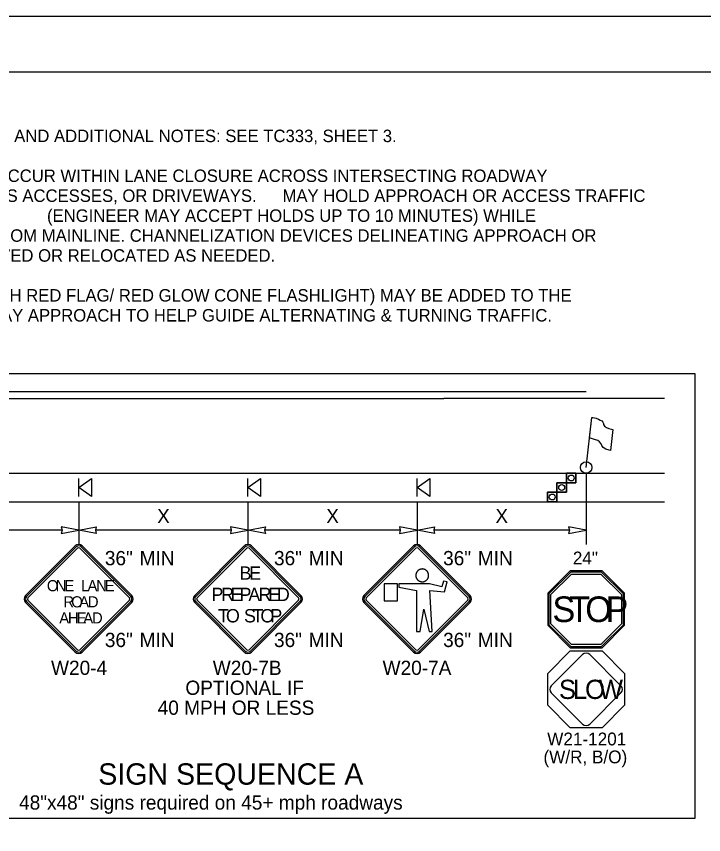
# Model space of a CAD drawing. Extents: x 99999.1 to 100095.7, y 99995 to 100010.7.
# Drawn here: x 100061.34 to 100065.2, y 100006.09 to 100010.687 of the extents above; entities that cross this region are included whole.
import ezdxf

# ---------------------------------------------------------------- set-up
doc = ezdxf.new("R2010")
doc.units = 0
for name, color, linetype in [('RD_ED_ShoulderPavedEdge', 7, 'Continuous'), ('RD_MK_LineDblYellowCenter', 7, 'Continuous'), ('RD_MK_LineEdgeWhite', 7, 'Continuous'), ('RD_MK_LineNoPass', 7, 'Continuous'), ('RD_MK_LineSkipCenter', 7, 'Continuous'), ('SH_DE_DetailHeading2Text', 7, 'Continuous'), ('SH_GI_GeneralNotesBodyText', 7, 'Continuous'), ('SH_GI_PlotLimits', 7, 'Continuous'), ('SH_GI_SheetBorder', 7, 'Continuous'), ('TR_SN_ConstructionSigns', 7, 'Continuous'), ('TR_WZ_FlaggingStation', 7, 'Continuous'), ('TR_WZ_PortableSignMountBlk-Org', 7, 'Continuous'), ('TR_WZ_TrafficCone', 7, 'Continuous'), ('TR_WZ_WorkZoneDetails', 7, 'Continuous'), ('TR_WZ_WorkZoneTextCurrent', 7, 'Continuous')]:
    doc.layers.add(name, color=color, linetype=linetype)

msp = doc.modelspace()

# ---------------------------------------------------------------- linework, layer by layer
at = {"layer": 'RD_ED_ShoulderPavedEdge'}
msp.add_line((100060.3, 100007.9602), (100064.9804, 100007.9602), dxfattribs=at)
at = {"layer": 'RD_MK_LineDblYellowCenter'}
for p, q in [((100060.3, 100008.5802), (100063.7402, 100008.5802)), ((100060.3, 100008.5402), (100063.7402, 100008.5402))]:
    msp.add_line(p, q, dxfattribs=at)
at = {"layer": 'RD_MK_LineEdgeWhite'}
msp.add_line((100060.3, 100008.1202), (100064.9804, 100008.1202), dxfattribs=at)
at = {"layer": 'RD_MK_LineNoPass'}
msp.add_line((100063.7402, 100008.5802), (100064.5402, 100008.5802), dxfattribs=at)
at = {"layer": 'RD_MK_LineSkipCenter'}
msp.add_lwpolyline([(100064.9804, 100008.5402), (100063.7402, 100008.5402)], dxfattribs=at)
at = {"layer": 'SH_GI_PlotLimits'}
msp.add_lwpolyline([(100059.0625, 99999.6875), (100076.0625, 99999.6875), (100076.0625, 100010.6875), (100059.0625, 100010.6875)], close=True, dxfattribs=at)
at = {"layer": 'SH_GI_SheetBorder'}
msp.add_line((100060, 100010.375), (100075.75, 100010.375), dxfattribs=at)
at = {"layer": 'TR_SN_ConstructionSigns'}
for p, q in [((100061.6703, 100007.712), (100061.3919, 100007.4336)), ((100061.6758, 100007.7065), (100061.3974, 100007.428)), ((100061.4051, 100007.4203), (100061.6835, 100007.6987)), ((100061.6968, 100007.6987), (100061.9752, 100007.4203)), ((100061.9829, 100007.428), (100061.7045, 100007.7065)), ((100061.9885, 100007.4336), (100061.71, 100007.712)), ((100062.6203, 100007.712), (100062.3419, 100007.4336)), ((100062.6258, 100007.7065), (100062.3474, 100007.428)), ((100062.3551, 100007.4203), (100062.6335, 100007.6987)), ((100062.6468, 100007.6987), (100062.9252, 100007.4203)), ((100062.9329, 100007.428), (100062.6545, 100007.7065)), ((100062.9385, 100007.4336), (100062.66, 100007.712)), ((100063.5703, 100007.712), (100063.2919, 100007.4336)), ((100063.5758, 100007.7065), (100063.2974, 100007.428)), ((100063.3051, 100007.4203), (100063.5835, 100007.6987)), ((100063.5968, 100007.6987), (100063.8752, 100007.4203)), ((100063.8829, 100007.428), (100063.6045, 100007.7065)), ((100063.8885, 100007.4336), (100063.61, 100007.712)), ((100063.5835, 100007.5502), (100063.5833, 100007.5483)), ((100063.5833, 100007.5483), (100063.5833, 100007.5464)), ((100063.5833, 100007.5464), (100063.5833, 100007.5445)), ((100063.5833, 100007.5445), (100063.5835, 100007.5426)), ((100063.5838, 100007.5522), (100063.5835, 100007.5502)), ((100063.5835, 100007.5426), (100063.5838, 100007.5407)), ((100063.5842, 100007.554), (100063.5838, 100007.5522)), ((100063.5838, 100007.5407), (100063.5842, 100007.5388)), ((100063.5846, 100007.5559), (100063.5842, 100007.554)), ((100063.5842, 100007.5388), (100063.5846, 100007.5369)), ((100063.5852, 100007.5577), (100063.5846, 100007.5559)), ((100063.5858, 100007.5595), (100063.5852, 100007.5577)), ((100063.5865, 100007.5613), (100063.5858, 100007.5595)), ((100063.5873, 100007.563), (100063.5865, 100007.5613)), ((100063.5883, 100007.5647), (100063.5873, 100007.563)), ((100063.5894, 100007.5664), (100063.5883, 100007.5647)), ((100063.5904, 100007.5679), (100063.5894, 100007.5664)), ((100063.5916, 100007.5694), (100063.5904, 100007.5679)), ((100063.5929, 100007.5709), (100063.5916, 100007.5694)), ((100063.5942, 100007.5722), (100063.5929, 100007.5709)), ((100063.5956, 100007.5735), (100063.5942, 100007.5722)), ((100063.5971, 100007.5747), (100063.5956, 100007.5735)), ((100063.5986, 100007.5759), (100063.5971, 100007.5747)), ((100063.6002, 100007.5769), (100063.5986, 100007.5759)), ((100063.6019, 100007.5779), (100063.6002, 100007.5769)), ((100063.6036, 100007.5788), (100063.6019, 100007.5779)), ((100063.6053, 100007.5796), (100063.6036, 100007.5788)), ((100063.6071, 100007.5803), (100063.6053, 100007.5796)), ((100063.6089, 100007.5809), (100063.6071, 100007.5803)), ((100063.6108, 100007.5814), (100063.6089, 100007.5809)), ((100063.6127, 100007.5818), (100063.6108, 100007.5814)), ((100063.6146, 100007.5821), (100063.6127, 100007.5818)), ((100063.6164, 100007.5823), (100063.6146, 100007.5821)), ((100063.6184, 100007.5824), (100063.6164, 100007.5823)), ((100063.6203, 100007.5824), (100063.6184, 100007.5824)), ((100063.6222, 100007.5823), (100063.6203, 100007.5824)), ((100063.6241, 100007.5821), (100063.6222, 100007.5823)), ((100063.626, 100007.5818), (100063.6241, 100007.5821)), ((100063.6279, 100007.5814), (100063.626, 100007.5818)), ((100063.6297, 100007.5809), (100063.6279, 100007.5814)), ((100063.6316, 100007.5803), (100063.6297, 100007.5809)), ((100063.6333, 100007.5796), (100063.6316, 100007.5803)), ((100063.6351, 100007.5788), (100063.6333, 100007.5796)), ((100063.6368, 100007.5779), (100063.6351, 100007.5788)), ((100063.6385, 100007.5769), (100063.6368, 100007.5779)), ((100063.64, 100007.5759), (100063.6385, 100007.5769)), ((100063.6416, 100007.5747), (100063.64, 100007.5759)), ((100063.643, 100007.5735), (100063.6416, 100007.5747)), ((100063.6445, 100007.5722), (100063.643, 100007.5735)), ((100063.6458, 100007.5709), (100063.6445, 100007.5722)), ((100063.647, 100007.5694), (100063.6458, 100007.5709)), ((100063.6482, 100007.5679), (100063.647, 100007.5694)), ((100063.6494, 100007.5664), (100063.6482, 100007.5679)), ((100063.6504, 100007.5647), (100063.6494, 100007.5664)), ((100063.6513, 100007.563), (100063.6504, 100007.5647)), ((100063.6521, 100007.5613), (100063.6513, 100007.563)), ((100063.6529, 100007.5595), (100063.6521, 100007.5613)), ((100063.6535, 100007.5577), (100063.6529, 100007.5595)), ((100063.6541, 100007.5559), (100063.6535, 100007.5577)), ((100063.6545, 100007.554), (100063.6541, 100007.5559)), ((100063.6541, 100007.5369), (100063.6545, 100007.5388)), ((100063.6549, 100007.5522), (100063.6545, 100007.554)), ((100063.6545, 100007.5388), (100063.6549, 100007.5407)), ((100063.6552, 100007.5502), (100063.6549, 100007.5522)), ((100063.6549, 100007.5407), (100063.6552, 100007.5426)), ((100063.6553, 100007.5483), (100063.6552, 100007.5502)), ((100063.6552, 100007.5426), (100063.6553, 100007.5445)), ((100063.6554, 100007.5464), (100063.6553, 100007.5483)), ((100063.6553, 100007.5445), (100063.6554, 100007.5464)), ((100064.4506, 100007.5722), (100064.3241, 100007.4457)), ((100064.4534, 100007.5655), (100064.3308, 100007.4429)), ((100064.3421, 100007.4383), (100064.4581, 100007.5542)), ((100064.6295, 100007.5722), (100064.4506, 100007.5722)), ((100064.6267, 100007.5655), (100064.4534, 100007.5655)), ((100064.4581, 100007.5542), (100064.6221, 100007.5542)), ((100064.6221, 100007.5542), (100064.7381, 100007.4383)), ((100064.7493, 100007.4429), (100064.6267, 100007.5655)), ((100064.7561, 100007.4457), (100064.6295, 100007.5722)), ((100063.4059, 100007.4991), (100063.4059, 100007.4044)), ((100063.4812, 100007.4991), (100063.4059, 100007.4991)), ((100063.4812, 100007.4044), (100063.4812, 100007.4991)), ((100063.6596, 100007.4991), (100063.4882, 100007.4991)), ((100063.4882, 100007.4991), (100063.4882, 100007.481)), ((100063.5846, 100007.5369), (100063.5852, 100007.5351)), ((100063.5852, 100007.5351), (100063.5858, 100007.5333)), ((100063.5858, 100007.5333), (100063.5865, 100007.5315)), ((100063.5865, 100007.5315), (100063.5873, 100007.5298)), ((100063.5873, 100007.5298), (100063.5883, 100007.5281)), ((100063.5883, 100007.5281), (100063.5894, 100007.5265)), ((100063.5894, 100007.5265), (100063.5904, 100007.5249)), ((100063.5904, 100007.5249), (100063.5916, 100007.5234)), ((100063.5916, 100007.5234), (100063.5929, 100007.522)), ((100063.5929, 100007.522), (100063.5942, 100007.5206)), ((100063.5942, 100007.5206), (100063.5956, 100007.5193)), ((100063.5956, 100007.5193), (100063.5971, 100007.5181)), ((100063.5971, 100007.5181), (100063.5986, 100007.5169)), ((100063.5986, 100007.5169), (100063.6002, 100007.5159)), ((100063.6002, 100007.5159), (100063.6019, 100007.5149)), ((100063.6019, 100007.5149), (100063.6036, 100007.514)), ((100063.6036, 100007.514), (100063.6053, 100007.5132)), ((100063.6053, 100007.5132), (100063.6071, 100007.5125)), ((100063.6071, 100007.5125), (100063.6089, 100007.5119)), ((100063.6089, 100007.5119), (100063.6108, 100007.5114)), ((100063.6108, 100007.5114), (100063.6127, 100007.511)), ((100063.6127, 100007.511), (100063.6146, 100007.5107)), ((100063.6146, 100007.5107), (100063.6164, 100007.5105)), ((100063.6164, 100007.5105), (100063.6184, 100007.5104)), ((100063.6184, 100007.5104), (100063.6203, 100007.5104)), ((100063.6203, 100007.5104), (100063.6222, 100007.5105)), ((100063.6222, 100007.5105), (100063.6241, 100007.5107)), ((100063.6241, 100007.5107), (100063.626, 100007.511)), ((100063.626, 100007.511), (100063.6279, 100007.5114)), ((100063.6279, 100007.5114), (100063.6297, 100007.5119)), ((100063.6297, 100007.5119), (100063.6316, 100007.5125)), ((100063.6316, 100007.5125), (100063.6333, 100007.5132)), ((100063.6333, 100007.5132), (100063.6351, 100007.514)), ((100063.6351, 100007.514), (100063.6368, 100007.5149)), ((100063.6368, 100007.5149), (100063.6385, 100007.5159)), ((100063.6385, 100007.5159), (100063.64, 100007.5169)), ((100063.64, 100007.5169), (100063.6416, 100007.5181)), ((100063.6416, 100007.5181), (100063.643, 100007.5193)), ((100063.643, 100007.5193), (100063.6445, 100007.5206)), ((100063.6445, 100007.5206), (100063.6458, 100007.522)), ((100063.6458, 100007.522), (100063.647, 100007.5234)), ((100063.647, 100007.5234), (100063.6482, 100007.5249)), ((100063.6482, 100007.5249), (100063.6494, 100007.5265)), ((100063.6494, 100007.5265), (100063.6504, 100007.5281)), ((100063.6504, 100007.5281), (100063.6513, 100007.5298)), ((100063.6513, 100007.5298), (100063.6521, 100007.5315)), ((100063.6521, 100007.5315), (100063.6529, 100007.5333)), ((100063.6529, 100007.5333), (100063.6535, 100007.5351)), ((100063.6535, 100007.5351), (100063.6541, 100007.5369)), ((100063.7291, 100007.482), (100063.6596, 100007.4991)), ((100063.7388, 100007.5148), (100063.7291, 100007.482)), ((100063.7588, 100007.5112), (100063.7388, 100007.5148)), ((100063.7438, 100007.4544), (100063.7588, 100007.5112)), ((100063.4882, 100007.481), (100063.5877, 100007.4612)), ((100063.5877, 100007.4612), (100063.5877, 100007.2309)), ((100063.6759, 100007.2309), (100063.6628, 100007.4613)), ((100063.6628, 100007.4613), (100063.7438, 100007.4544)), ((100061.6835, 100007.1286), (100061.4051, 100007.4071)), ((100061.9752, 100007.4071), (100061.6968, 100007.1286)), ((100062.6335, 100007.1286), (100062.3551, 100007.4071)), ((100062.9252, 100007.4071), (100062.6468, 100007.1286)), ((100063.5835, 100007.1286), (100063.3051, 100007.4071)), ((100063.4059, 100007.4044), (100063.4812, 100007.4044)), ((100063.8752, 100007.4071), (100063.5968, 100007.1286)), ((100064.3241, 100007.4457), (100064.3241, 100007.2668)), ((100064.3308, 100007.4429), (100064.3308, 100007.2696)), ((100064.3421, 100007.2742), (100064.3421, 100007.4383)), ((100064.7381, 100007.4383), (100064.7381, 100007.2742)), ((100064.7493, 100007.2696), (100064.7493, 100007.4429)), ((100064.7561, 100007.2668), (100064.7561, 100007.4457)), ((100061.3919, 100007.3938), (100061.6703, 100007.1154)), ((100061.3974, 100007.3993), (100061.6758, 100007.1209)), ((100061.7045, 100007.1209), (100061.9829, 100007.3993)), ((100061.71, 100007.1154), (100061.9885, 100007.3938)), ((100062.3419, 100007.3938), (100062.6203, 100007.1154)), ((100062.3474, 100007.3993), (100062.6258, 100007.1209)), ((100062.6545, 100007.1209), (100062.9329, 100007.3993)), ((100062.66, 100007.1154), (100062.9385, 100007.3938)), ((100063.2919, 100007.3938), (100063.5703, 100007.1154)), ((100063.2974, 100007.3993), (100063.5758, 100007.1209)), ((100063.6045, 100007.1209), (100063.8829, 100007.3993)), ((100063.6079, 100007.2309), (100063.6276, 100007.3576)), ((100063.61, 100007.1154), (100063.8885, 100007.3938)), ((100063.6276, 100007.3576), (100063.6579, 100007.2309)), ((100064.3241, 100007.2668), (100064.4506, 100007.1402)), ((100064.3308, 100007.2696), (100064.4534, 100007.147)), ((100064.4581, 100007.1582), (100064.3421, 100007.2742)), ((100064.7381, 100007.2742), (100064.6221, 100007.1582)), ((100064.6267, 100007.147), (100064.7493, 100007.2696)), ((100064.6295, 100007.1402), (100064.7561, 100007.2668)), ((100063.5877, 100007.2309), (100063.6079, 100007.2309)), ((100063.6579, 100007.2309), (100063.6759, 100007.2309)), ((100064.4506, 100007.1402), (100064.6295, 100007.1402)), ((100064.4534, 100007.147), (100064.6267, 100007.147)), ((100064.6221, 100007.1582), (100064.4581, 100007.1582)), ((100064.5197, 100007.1019), (100064.3444, 100006.9266)), ((100064.7357, 100006.9266), (100064.5604, 100007.1019)), ((100064.3444, 100006.8859), (100064.5197, 100006.7106)), ((100064.5604, 100006.7106), (100064.7357, 100006.8859))]:
    msp.add_line(p, q, dxfattribs=at)
msp.add_lwpolyline([(100064.7561, 100006.9957), (100064.7561, 100006.8168), (100064.6295, 100006.6902), (100064.4506, 100006.6902), (100064.3241, 100006.8168), (100064.3241, 100006.9957), (100064.4506, 100007.1222), (100064.6295, 100007.1222)], close=True, dxfattribs=at)
for centre, radius, start, end in [((100061.6902, 100007.6921), 0.0281, 45, 135), ((100061.6902, 100007.6921), 0.0203, 45, 135), ((100061.6902, 100007.6921), 0.00937, 45, 135), ((100062.6402, 100007.6921), 0.0281, 45, 135), ((100062.6402, 100007.6921), 0.0203, 45, 135), ((100062.6402, 100007.6921), 0.00937, 45, 135), ((100063.5902, 100007.6921), 0.0281, 45, 135), ((100063.5902, 100007.6921), 0.0203, 45, 135), ((100063.5902, 100007.6921), 0.00937, 45, 135), ((100061.4117, 100007.4137), 0.0281, 135, 225), ((100061.4117, 100007.4137), 0.0203, 135, 225), ((100061.4117, 100007.4137), 0.00937, 135, 225), ((100061.9686, 100007.4137), 0.00937, 315, 45), ((100061.9686, 100007.4137), 0.0203, 315, 45), ((100061.9686, 100007.4137), 0.0281, 315, 45), ((100062.3617, 100007.4137), 0.0281, 135, 225), ((100062.3617, 100007.4137), 0.0203, 135, 225), ((100062.3617, 100007.4137), 0.00937, 135, 225), ((100062.9186, 100007.4137), 0.00937, 315, 45), ((100062.9186, 100007.4137), 0.0203, 315, 45), ((100062.9186, 100007.4137), 0.0281, 315, 45), ((100063.3117, 100007.4137), 0.0281, 135, 225), ((100063.3117, 100007.4137), 0.0203, 135, 225), ((100063.3117, 100007.4137), 0.00937, 135, 225), ((100063.8686, 100007.4137), 0.00937, 315, 45), ((100063.8686, 100007.4137), 0.0203, 315, 45), ((100063.8686, 100007.4137), 0.0281, 315, 45), ((100061.6902, 100007.1353), 0.00937, 225, 315), ((100062.6402, 100007.1353), 0.00937, 225, 315), ((100063.5902, 100007.1353), 0.00937, 225, 315), ((100061.6902, 100007.1353), 0.0281, 225, 315), ((100061.6902, 100007.1353), 0.0203, 225, 315), ((100062.6402, 100007.1353), 0.0281, 225, 315), ((100062.6402, 100007.1353), 0.0203, 225, 315), ((100063.5902, 100007.1353), 0.0281, 225, 315), ((100063.5902, 100007.1353), 0.0203, 225, 315), ((100064.5401, 100007.0815), 0.0288, 45, 135), ((100064.3648, 100006.9062), 0.0288, 135, 225), ((100064.7153, 100006.9062), 0.0288, 315, 45), ((100064.5401, 100006.731), 0.0288, 225, 315)]:
    msp.add_arc(centre, radius, start, end, dxfattribs=at)
at = {"layer": 'TR_WZ_FlaggingStation'}
for p, q in [((100064.5402, 100008.1527), (100064.5722, 100008.4337)), ((100064.5592, 100008.3196), (100064.5723, 100008.434)), ((100064.6902, 100008.3662), (100064.6769, 100008.249)), ((100064.5592, 100008.3196), (100064.5592, 100008.3196))]:
    msp.add_line(p, q, dxfattribs=at)
for points in [[(100064.5723, 100008.434), (100064.578, 100008.4327), (100064.5958, 100008.4293), (100064.6097, 100008.4251), (100064.6193, 100008.419), (100064.6279, 100008.4143), (100064.6335, 100008.4075), (100064.6378, 100008.3996), (100064.6383, 100008.3934), (100064.6437, 100008.3842), (100064.6545, 100008.3768), (100064.6669, 100008.3716), (100064.6902, 100008.3662)], [(100064.6769, 100008.249), (100064.6687, 100008.2504), (100064.6511, 100008.255), (100064.6354, 100008.2655), (100064.6289, 100008.2761), (100064.625, 100008.2864), (100064.6159, 100008.2973), (100064.6049, 100008.3035), (100064.5876, 100008.3106), (100064.5592, 100008.3196)]]:
    msp.add_lwpolyline(points, dxfattribs=at)
msp.add_circle((100064.5402, 100008.1527), 0.0325, dxfattribs=at)
at = {"layer": 'TR_WZ_PortableSignMountBlk-Org'}
for p, q in [((100061.6902, 100007.9902), (100061.6902, 100008.0902)), ((100062.6402, 100007.9902), (100062.6402, 100008.0902)), ((100063.5902, 100007.9902), (100063.5902, 100008.0902))]:
    msp.add_line(p, q, dxfattribs=at)
for points in [[(100061.6902, 100008.0401), (100061.762, 100008.0902), (100061.762, 100007.9902)], [(100062.6402, 100008.0401), (100062.712, 100008.0902), (100062.712, 100007.9902)], [(100063.5902, 100008.0401), (100063.662, 100008.0902), (100063.662, 100007.9902)]]:
    msp.add_lwpolyline(points, close=True, dxfattribs=at)
at = {"layer": 'TR_WZ_TrafficCone'}
for points in [[(100064.4295, 100008.1202), (100064.4828, 100008.1202), (100064.4828, 100008.0669), (100064.4295, 100008.0669), (100064.4295, 100008.1202)], [(100064.4295, 100008.0669), (100064.4828, 100008.0669), (100064.4828, 100008.1202), (100064.4295, 100008.1202), (100064.4295, 100008.0669)], [(100064.3762, 100008.0669), (100064.4295, 100008.0669), (100064.4295, 100008.0136), (100064.3762, 100008.0136), (100064.3762, 100008.0669)], [(100064.3762, 100008.0136), (100064.4295, 100008.0136), (100064.4295, 100008.0669), (100064.3762, 100008.0669), (100064.3762, 100008.0136)], [(100064.3228, 100008.0136), (100064.3762, 100008.0136), (100064.3762, 100007.9602), (100064.3228, 100007.9602), (100064.3228, 100008.0136)], [(100064.3228, 100007.9602), (100064.3762, 100007.9602), (100064.3762, 100008.0136), (100064.3228, 100008.0136), (100064.3228, 100007.9602)]]:
    msp.add_lwpolyline(points, dxfattribs=at)
for centre in [(100064.4562, 100008.0936), (100064.4028, 100008.0402), (100064.3495, 100007.9869)]:
    msp.add_circle(centre, 0.0167, dxfattribs=at)
at = {"layer": 'TR_WZ_WorkZoneDetails'}
for p, q in [((100064.5402, 100008.1202), (100064.5402, 100007.7202)), ((100061.6902, 100007.9602), (100061.6902, 100007.7202)), ((100062.6402, 100007.9602), (100062.6402, 100007.7202)), ((100063.5902, 100007.9602), (100063.5902, 100007.7202)), ((100061.5964, 100007.8002), (100060.8339, 100007.8002)), ((100062.5464, 100007.8002), (100061.7839, 100007.8002)), ((100063.4964, 100007.8002), (100062.7339, 100007.8002)), ((100064.4464, 100007.8002), (100063.6839, 100007.8002))]:
    msp.add_line(p, q, dxfattribs=at)
for points in [[(100061.6902, 100007.8002), (100061.5919, 100007.8195), (100061.5964, 100007.8002), (100061.5919, 100007.781)], [(100061.6902, 100007.8002), (100061.7884, 100007.8195), (100061.7839, 100007.8002), (100061.7884, 100007.781)], [(100062.6402, 100007.8002), (100062.5419, 100007.8195), (100062.5464, 100007.8002), (100062.5419, 100007.781)], [(100062.6402, 100007.8002), (100062.7384, 100007.8195), (100062.7339, 100007.8002), (100062.7384, 100007.781)], [(100063.5902, 100007.8002), (100063.4919, 100007.8195), (100063.4964, 100007.8002), (100063.4919, 100007.781)], [(100063.5902, 100007.8002), (100063.6884, 100007.8195), (100063.6839, 100007.8002), (100063.6884, 100007.781)], [(100064.5402, 100007.8002), (100064.4419, 100007.8195), (100064.4464, 100007.8002), (100064.4419, 100007.781)]]:
    msp.add_lwpolyline(points, close=True, dxfattribs=at)
at = {"layer": 'TR_WZ_WorkZoneTextCurrent'}
msp.add_lwpolyline([(100060.1, 100008.6802), (100065.15, 100008.6802), (100065.15, 100006.1804), (100060.1, 100006.1804)], close=True, dxfattribs=at)

# ---------------------------------------------------------------- texts
at = {"layer": 'SH_DE_DetailHeading2Text'}
msp.add_text('SIGN SEQUENCE A', height=0.12, rotation=360, dxfattribs=at).set_placement((100061.7998, 100006.3705))
at = {"layer": 'SH_GI_GeneralNotesBodyText'}
for s, p in [('15. FOR LEGEND, TABLES, AND ADDITIONAL NOTES: SEE TC333, SHEET 3.', (100060.1, 100009.981)), ('16. WORK MAY BRIEFLY OCCUR WITHIN LANE CLOSURE ACROSS INTERSECTING ROADWAY ', (100060.1, 100009.757)), ('APPROACHES, BUSINESS ACCESSES, OR DRIVEWAYS. ', (100060.172, 100009.645)), ('MAY HOLD APPROACH OR ACCESS TRAFFIC ', (100062.8346, 100009.645)), (' (ENGINEER MAY ACCEPT HOLDS UP TO 10 MINUTES) WHILE ', (100061.486, 100009.533)), ('RESTRICTING TURNS FROM MAINLINE. CHANNELIZATION DEVICES DELINEATING APPROACH OR ', (100060.172, 100009.421)), ('ACCESS MAY BE REMOVED OR RELOCATED AS NEEDED.', (100060.172, 100009.309)), ('17. SINGLE FLAGGER (WITH RED FLAG/ RED GLOW CONE FLASHLIGHT) MAY BE ADDED TO THE ', (100060.1, 100009.085)), ('INTERSECTING ROADWAY APPROACH TO HELP GUIDE ALTERNATING & TURNING TRAFFIC.', (100060.172, 100008.973))]:
    msp.add_text(s, height=0.07, rotation=360, dxfattribs=at).set_placement(p)
at = {"layer": 'TR_SN_ConstructionSigns'}
for s, height, p in [('36"', 0.08, (100061.8369, 100007.6035)), ('MIN', 0.08, (100062.0319, 100007.6035)), ('36"', 0.08, (100062.7869, 100007.6035)), ('MIN', 0.08, (100062.9819, 100007.6035)), ('36"', 0.08, (100063.7369, 100007.6035)), ('MIN', 0.08, (100063.9319, 100007.6035)), ('36"', 0.08, (100061.8369, 100007.1439)), ('MIN', 0.08, (100062.0319, 100007.1439)), ('36"', 0.08, (100062.7869, 100007.1439)), ('MIN', 0.08, (100062.9819, 100007.1439)), ('36"', 0.08, (100063.7369, 100007.1439)), ('MIN', 0.08, (100063.9319, 100007.1439)), ('W20-4', 0.08, (100061.5347, 100006.9871)), ('W20-7B', 0.08, (100062.4432, 100006.9871)), ('W20-7A', 0.08, (100063.3969, 100006.9871)), ('OPTIONAL IF', 0.08, (100062.2892, 100006.8751)), ('40 MPH OR LESS', 0.08, (100062.1337, 100006.7631)), ('W21-1201', 0.072, (100064.3213, 100006.5913)), ('(W/R, B/O)', 0.072, (100064.3004, 100006.4905))]:
    msp.add_text(s, height=height, rotation=360, dxfattribs=at).set_placement(p)
for s, height, p in [('24"', 0.072, (100064.4654, 100007.6082)), ('B', 0.075, (100062.5939, 100007.5222)), ('E', 0.075, (100062.6482, 100007.5222)), ('O', 0.0625, (100061.5114, 100007.4574)), ('N', 0.0625, (100061.5608, 100007.4574)), ('E', 0.0625, (100061.6095, 100007.4574)), ('L', 0.0625, (100061.7039, 100007.4574)), ('A', 0.0625, (100061.7395, 100007.4574)), ('N', 0.0625, (100061.7883, 100007.4574)), ('E', 0.0625, (100061.837, 100007.4574)), ('P', 0.075, (100062.4353, 100007.4022)), ('R', 0.075, (100062.4905, 100007.4022)), ('E', 0.075, (100062.5437, 100007.4022)), ('P', 0.075, (100062.5932, 100007.4022)), ('A', 0.075, (100062.6431, 100007.4022)), ('R', 0.075, (100062.7004, 100007.4022)), ('E', 0.075, (100062.7536, 100007.4022)), ('D', 0.075, (100062.8031, 100007.4022)), ('R', 0.0625, (100061.6039, 100007.3668)), ('O', 0.0625, (100061.6483, 100007.3668)), ('A', 0.0625, (100061.6927, 100007.3668)), ('D', 0.0625, (100061.7414, 100007.3668)), ('S', 0.144, (100064.3507, 100007.2842)), ('T', 0.144, (100064.4443, 100007.2842)), ('O', 0.144, (100064.535, 100007.2842)), ('P', 0.144, (100064.6488, 100007.2842)), ('T', 0.075, (100062.4719, 100007.2822)), ('O', 0.075, (100062.517, 100007.2822)), ('S', 0.075, (100062.6185, 100007.2822)), ('T', 0.075, (100062.6656, 100007.2822)), ('O', 0.075, (100062.7107, 100007.2822)), ('P', 0.075, (100062.7664, 100007.2822)), ('A', 0.0625, (100061.5808, 100007.2762)), ('H', 0.0625, (100061.6295, 100007.2762)), ('E', 0.0625, (100061.6783, 100007.2762)), ('A', 0.0625, (100061.7158, 100007.2762)), ('D', 0.0625, (100061.7645, 100007.2762)), ('S', 0.108, (100064.3873, 100006.8522)), ('L', 0.108, (100064.4661, 100006.8522)), ('O', 0.108, (100064.5341, 100006.8522)), ('W', 0.108, (100064.6108, 100006.8522))]:
    msp.add_text(s, height=height, dxfattribs=at).set_placement(p)
at = {"layer": 'TR_WZ_WorkZoneTextCurrent'}
for p in [(100062.1304, 100007.8402), (100063.0804, 100007.8402), (100064.0304, 100007.8402)]:
    msp.add_text('X', height=0.08, rotation=360, dxfattribs=at).set_placement(p)
msp.add_text('48"x48" signs required on 45+ mph roadways', height=0.08, dxfattribs=at).set_placement((100061.3551, 100006.2305))

doc.saveas('drawing.dxf')
